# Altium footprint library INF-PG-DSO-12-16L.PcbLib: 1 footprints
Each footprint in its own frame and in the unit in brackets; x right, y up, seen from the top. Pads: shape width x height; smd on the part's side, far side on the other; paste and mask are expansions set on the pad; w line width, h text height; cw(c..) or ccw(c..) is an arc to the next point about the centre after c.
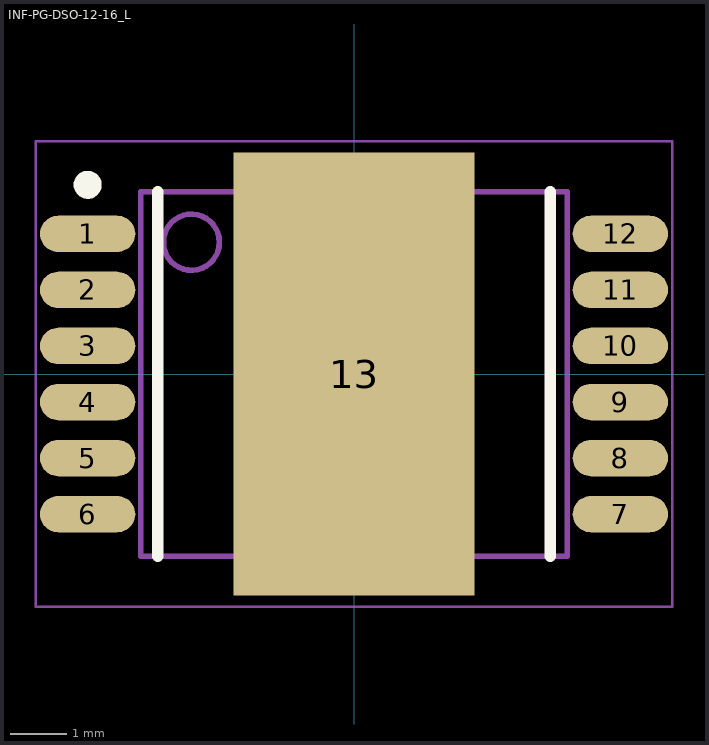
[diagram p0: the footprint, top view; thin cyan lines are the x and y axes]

## INF-PG-DSO-12-16_L [mm] "SOP, 12-Leads, Body 7.5x6.4mm, Pitch 1mm, Thermal Pad 4.3X7.9mm, IPC High Density"
height 2.6
pads (13):
  oval 1.7x0.65 smd: 1(-4.75,2.5) 2(-4.75,1.5) 3(-4.75,0.5) 4(-4.75,-0.5) 5(-4.75,-1.5) 6(-4.75,-2.5) 7(4.75,-2.5) 8(4.75,-1.5) 9(4.75,-0.5) 10(4.75,0.5) 11(4.75,1.5) 12(4.75,2.5)
  rect 4.3x7.9 smd: 13(0,0)
Top Overlay:
  circle w0.25: c-4.75,3.375 r0.125
  lines w0.2: -3.5,-3.25 -3.5,3.25 ; 3.5,-3.25 3.5,3.25
Mechanical 13:
  circle w0.1: c-2.9,2.35 r0.5
  lines w0.1: -3.8,-3.25 3.8,-3.25 3.8,3.25 -3.8,3.25 -3.8,-3.25
Mechanical 15:
  lines w0.05: -5.675,-4.15 5.675,-4.15 5.675,4.15 -5.675,4.15 -5.675,-4.15
  lines w0.1: -0.5,0 0.5,0 ; 0,-0.5 0,0.5
3D body: height 2.6, standoff 0, extent -3.8,-3.25 3.8,3.25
